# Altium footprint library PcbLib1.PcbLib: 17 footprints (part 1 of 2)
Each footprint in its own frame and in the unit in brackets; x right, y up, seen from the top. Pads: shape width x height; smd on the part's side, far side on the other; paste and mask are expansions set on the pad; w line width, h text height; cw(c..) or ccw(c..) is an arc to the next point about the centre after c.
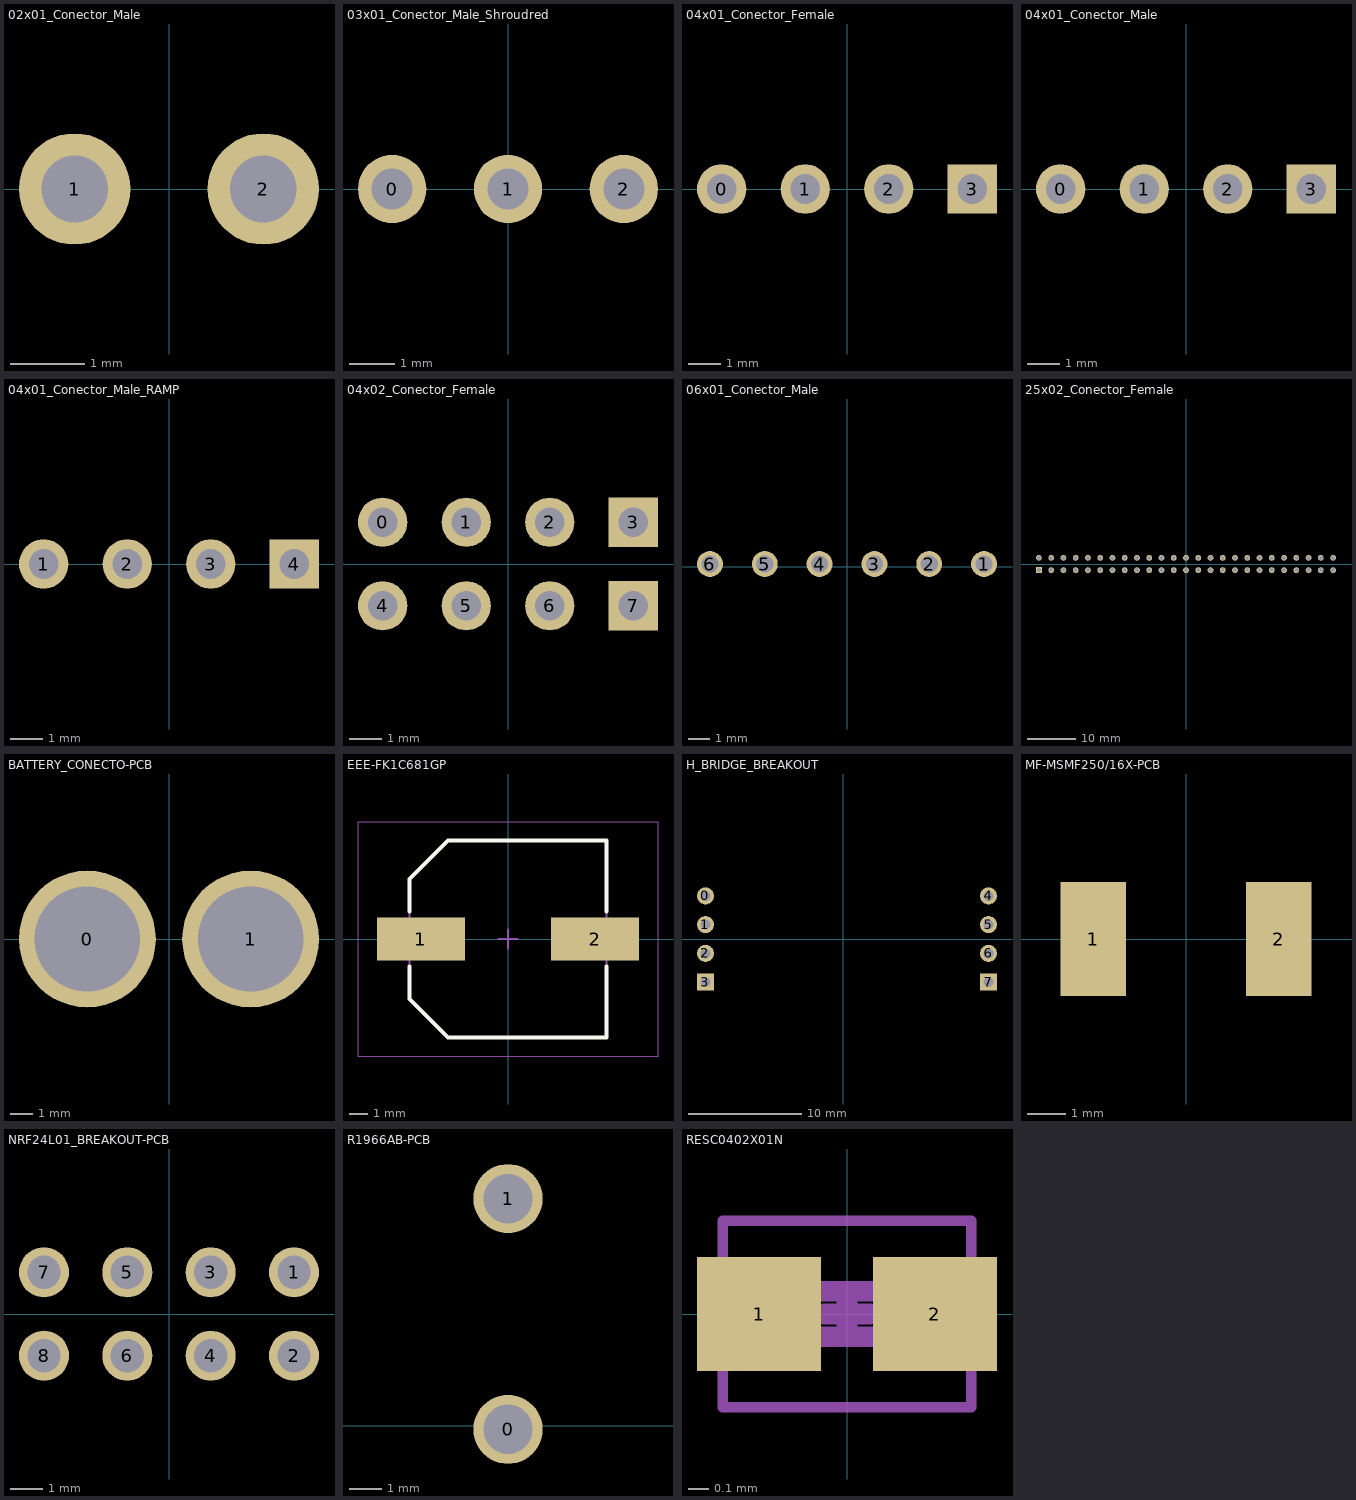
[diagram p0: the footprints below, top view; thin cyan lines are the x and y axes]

## 02x01_Conector_Male [mm] "0022112022"
pads (2):
  round 1.5 hole 0.9: 1(-1.27,0) 2(1.27,0)
3D body "022112022.stp": height 3.14, standoff -11.08, extent -2.464,-3.251 2.464,3.099

## 03x01_Conector_Male_Shroudred [mm] "B3B-XH-A(LF)(SN)"
pads (3):
  round 1.5 hole 0.9: 0(-2.54,0) 1(0,0) 2(2.54,0)
3D body "User Library-XH-3P_2_5_Silver.STEP": height 3.1, standoff -7.4, extent -4.953,-3.383 4.947,2.367

## 04x01_Conector_Female [mm] "PPPC041LFBN-RC"
pads (4):
  round 1.5 hole 0.9: 0(-3.81,0) 1(-1.27,0) 2(1.27,0)
  rect 1.5x1.5 hole 0.9: 3(3.81,0)
3D body "_ _ _C041LFBN-RC.STEP": height 8.5, standoff -3.2, extent -5.33,-1.27 5.33,1.27

## 04x01_Conector_Male [mm] "0022032041"
pads (4):
  round 1.5 hole 0.9: 0(-3.81,0) 1(-1.27,0) 2(1.27,0)
  rect 1.5x1.5 hole 0.9: 3(3.81,0)
3D body "022032041.stp": height 10.84, standoff -3.38, extent -4.953,-1.181 4.953,1.181

## 04x01_Conector_Male_RAMP [mm] "0022232041"
pads (4):
  round 1.5 hole 0.9: 1(-3.81,0) 2(-1.27,0) 3(1.27,0)
  rect 1.5x1.5 hole 0.9: 4(3.81,0)
3D body "022232041.stp": height 3.04, standoff -11.18, extent -5.004,-3.175 5.004,3.175

## 04x02_Conector_Female [mm] "PPPC042LFBN-RC"
pads (8):
  round 1.5 hole 0.9: 0(-3.81,1.27) 1(-1.27,1.27) 2(1.27,1.27) 4(-3.81,-1.27) 5(-1.27,-1.27) 6(1.27,-1.27)
  rect 1.5x1.5 hole 0.9: 3(3.81,1.27) 7(3.81,-1.27)
3D body "_ _ _C042LFBN-RC.STEP": height 8.52, standoff -3.18, extent -5.304,-2.549 5.36,2.531

## 06x01_Conector_Male [mil] "0022112062"
pads (6):
  round 47.25 hole 31.5: 1(250,5) 2(150,5) 3(50,5) 4(-50,5) 5(-150,5) 6(-250,5)
3D body "022112062.stp": height 123.76, standoff -436.24, extent -297,-115 297,135

## 25x02_Conector_Female [mil] "SFH11-PBPC-D25-ST-BK"
pads (50):
  rect 47.25x47.25 hole 31.5: 1(-1200,-50)
  round 47.25 hole 31.5: 2(-1200,50) 3(-1100,-50) 4(-1100,50) 5(-1000,-50) 6(-1000,50) 7(-900,-50) 8(-900,50) 9(-800,-50) 10(-800,50) 11(-700,-50) 12(-700,50) 13(-600,-50) 14(-600,50) 15(-500,-50) 16(-500,50) 17(-400,-50) 18(-400,50) 19(-300,-50) 20(-300,50) 21(-200,-50) 22(-200,50) 23(-100,-50) 24(-100,50) 25(0,-50) 26(0,50) 27(100,-50) 28(100,50) 29(200,-50) 30(200,50) 31(300,-50) 32(300,50) 33(400,-50) 34(400,50) 35(500,-50) 36(500,50) 37(600,-50) 38(600,50) 39(700,-50) 40(700,50) 41(800,-50) 42(800,50) 43(900,-50) 44(900,50) 45(1000,-50) 46(1000,50) 47(1100,-50) 48(1100,50) 49(1200,-50) 50(1200,50)
3D body "SFH11-P_ _C-D25-ST-_ _-M181.STEP": height 332.68, standoff -127.95, extent -1350,-121.22 1350,115

## BATTERY_CONECTO-PCB [mm]
pads (2):
  round 6 hole 4.62: 0(-3.58,0) 1(3.58,0)
3D body "User Library-XT60 male.STEP": height 16.4, standoff -4.8, extent -7.823,-4.191 8.077,3.959

## EEE-FK1C681GP [mm] "Aluminum Electrolytic Capacitor, Body 10,30x10,30x10,50mm, IPC Low Density"
height 10.5
pads (2):
  rect 4.7x2.3 smd: 1(-4.65,0) 2(4.65,0)
Top Overlay:
  lines w0.2: -5.25,-1.45 -5.25,-3.2 -3.2,-5.25 5.25,-5.25 5.25,-1.45 ; -5.25,1.45 -5.25,3.2 -3.2,5.25 5.25,5.25 5.25,1.45
Mechanical 13:
  lines w0.1: -5.25,-3.2 -5.25,3.2 -3.2,5.25 5.25,5.25 5.25,-5.25 -3.2,-5.25 -5.25,-3.2
Mechanical 15:
  lines w0.05: -8,-6.25 8,-6.25 8,6.25 -8,6.25 -8,-6.25
  lines w0.1: -0.5,0 0.5,0 ; 0,-0.5 0,0.5
3D body "SW3dPS-capg.STEP": height 10.41, standoff -0.05, extent -5.65,-5.207 5.65,5.093

## H_BRIDGE_BREAKOUT [mm]
pads (8):
  round 1.5 hole 0.9: 0(-12.173,3.81) 1(-12.173,1.27) 2(-12.173,-1.27) 4(12.827,3.81) 5(12.827,1.27) 6(12.827,-1.27)
  rect 1.5x1.5 hole 0.9: 3(-12.173,-3.81) 7(12.827,-3.81)
3D body "motor_driver.step": height 9.95, standoff -4.34, extent -13.824,-7.112 14.354,6.985

## MF-MSMF250/16X-PCB [mm] "Chip PTC RESETTABLE"
height 0.85
pads (2):
  rect 1.68x2.95 smd: 1(-2.39,0) 2(2.39,0)
3D body "mf-msmf250_16x (2).stp": height 1.15, standoff 0, extent -2.3,-1.62 2.3,1.62

## NRF24L01_BREAKOUT-PCB [mil]
pads (8):
  round 60 hole 40.16: 1(150,50) 2(150,-50) 3(50,50) 4(50,-50) 5(-50,50) 6(-50,-50) 7(-150,50) 8(-150,-50)

## PCBComponent_1 - duplicate [mil]

## R1966AB-PCB [mm] "SWITCH ROCKER SPST 15A 125V"
pads (2):
  round 2.1 hole 1.5: 0(10.541,-0.117)
  round 2.1 hole 1.5 paste+0: 1(10.541,6.883)
3D body "R1966ABLKBLKFR.stp": height 15.6, standoff -3.8, extent -11.377,-10.668 11.123,10.276

## RESC0402X01N [mm] "Chip Resistor, 2-Leads, Body 0,40x0,20mm, IPC Medium Density"
height 0.13
pads (2):
  rect 0.6x0.55 smd: 1(-0.425,0) 2(0.425,0)
Mechanical 13:
  lines w0.1: -0.21,-0.11 -0.21,0.11 0.21,0.11 0.21,-0.11 -0.21,-0.11
Mechanical 15:
  lines w0.05: -0.6,-0.45 -0.6,0.45 0.6,0.45 0.6,-0.45 -0.6,-0.45
  lines w0.1: -0.11,0 0.11,0 ; 0,-0.11 0,0.11
3D body: height 0.13, standoff 0, extent -0.21,-0.11 0.21,0.11
3D body: height 0.13, standoff 0, extent -0.21,-0.11 0.21,0.11
3D body: height 0.13, standoff 0, extent -0.21,-0.11 0.21,0.11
